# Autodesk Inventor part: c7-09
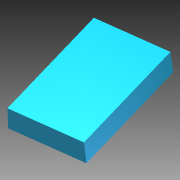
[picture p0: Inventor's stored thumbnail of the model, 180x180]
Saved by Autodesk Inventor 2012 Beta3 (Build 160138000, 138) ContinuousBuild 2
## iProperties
Created: 2010-12
Part Number: c7-09
Material: Default
Document SubType Name: Modeling
Designer: Beta-8540w
Density: 1 g/cm^3
Author: Beta-8540w
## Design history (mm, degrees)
sketch "Sketch1"
  geometry: L1 (-25, 0)-(25, 0); L2 (25, 0)-(25, 80); L3 (25, 80)-(-25, 80); L4 (-25, 80)-(-25, 0); 2 further points
  constraints: 8 end point, 2 parallel, 1 coincident, 1 horizontal, 1 midpoint, 1 perpendicular
  dimensions: "d0" = 50 distance of L3.end L2.end; "d1" = 80 distance of L2.end L1.end
extrude "Extrusion1" new body sketch "Sketch1" distance "d2" = 15; taper "d3" = 0 deg
feature "FaceDraft1" dims angle "d4" = -2 deg
body "Solid1"
